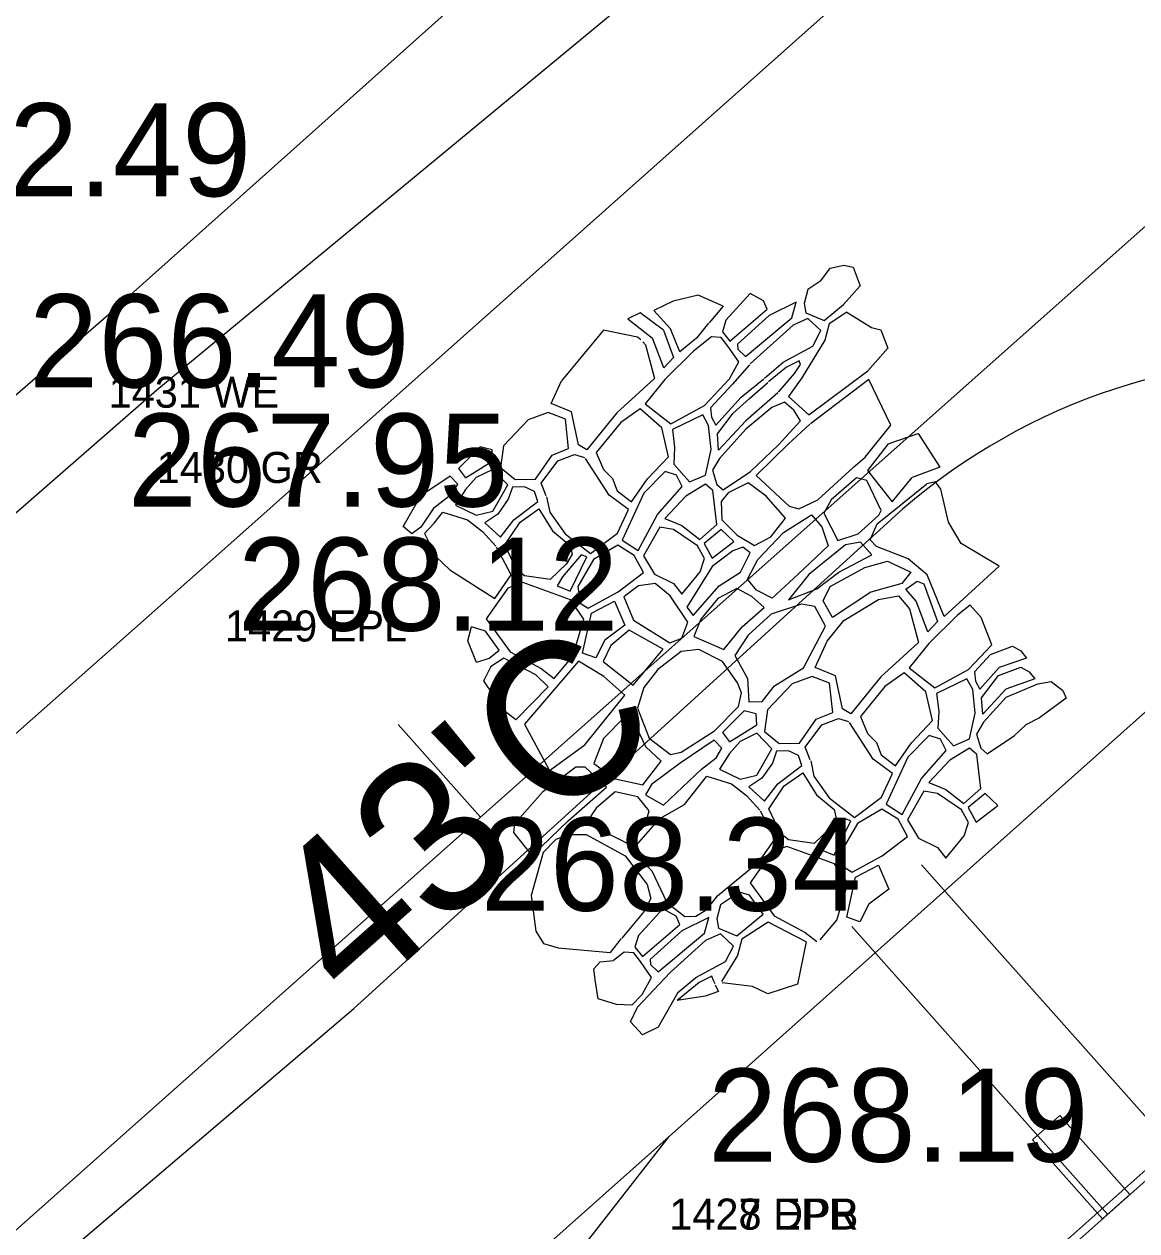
# Model space of a CAD drawing. Extents: x 49683 to 58852, y 49525 to 54803.
# Drawn here: x 55220.91 to 55256.78, y 53061.78 to 53100.69 of the extents above; entities that cross this region are included whole.
import ezdxf

# ---------------------------------------------------------------- set-up
doc = ezdxf.new("R2010")
doc.units = 0
for name, color, linetype in [('Level 1', 7, 'Continuous'), ('Level 10', 7, 'Continuous'), ('Level 15', 7, 'Continuous'), ('Level 18', 7, 'Continuous'), ('Level 27', 7, 'Continuous'), ('Level 3', 7, 'Continuous'), ('Level 32', 7, 'Continuous'), ('Level 48', 7, 'Continuous'), ('Level 53', 7, 'Continuous'), ('Level 57', 7, 'Continuous'), ('Level 58', 7, 'Continuous'), ('Level 60', 7, 'Continuous'), ('Level 7', 7, 'Continuous'), ('Level 8', 7, 'Continuous')]:
    doc.layers.add(name, color=color, linetype=linetype)

msp = doc.modelspace()

# ---------------------------------------------------------------- linework, layer by layer
at = {"layer": 'Level 1'}
for p, q in [((52544.807, 50683.302), (55534.583, 53340.862)), ((55235.619, 53075.118), (55232.962, 53078.107))]:
    msp.add_line(p, q, dxfattribs=at)
at = {"layer": 'Level 10'}
for p, q in [((55223.631, 53091.32), (55261.669, 53125.363)), ((55039.313, 52932.122), (55223.631, 53091.32))]:
    msp.add_line(p, q, dxfattribs=at)
at = {"layer": 'Level 15'}
for p, q in [((55258.079, 53064.31), (55249.837, 53073.583)), ((55255.837, 53062.317), (55247.596, 53071.588)), ((55253.595, 53060.324), (55265.526, 53070.929))]:
    msp.add_line(p, q, dxfattribs=at)
for points in [[(55246.591, 53092.41), (55246.89, 53092.815), (55247.336, 53092.921), (55247.639, 53092.849), (55247.862, 53092.252), (55247.324, 53091.649)], [(55246.591, 53092.41), (55246.175, 53092.126), (55246.052, 53091.685), (55246.113, 53091.379), (55246.701, 53091.134), (55247.324, 53091.649)], [(55242.635, 53091.946), (55241.828, 53091.756), (55241.207, 53091.455), (55241.748, 53090.865)], [(55243.442, 53091.595), (55242.635, 53091.946)], [(55244.313, 53092.002), (55243.528, 53091.143), (55243.417, 53090.763), (55243.662, 53090.469), (55244.864, 53091.5), (55244.741, 53091.769), (55244.313, 53092.002)], [(55243.442, 53091.595), (55242.992, 53091.059)], [(55241.519, 53090.817), (55240.772, 53091.384), (55240.368, 53091.189), (55241.169, 53090.559)], [(55242.976, 53091.044), (55242.587, 53090.557), (55242.049, 53090.124), (55241.748, 53090.865)], [(55244.774, 53089.277), (55245.376, 53089.785), (55246.332, 53090.301), (55246.59, 53090.804), (55246.174, 53091.195), (55245.696, 53090.986), (55244.319, 53089.732)], [(55247.435, 53091.399), (55246.86, 53091.024), (55246.725, 53090.497), (55245.976, 53089.284), (55245.546, 53088.683), (55246.207, 53088.095), (55248.103, 53089.509)], [(55247.435, 53091.399), (55248.226, 53090.906), (55248.53, 53090.834), (55248.752, 53090.237), (55248.103, 53089.509)], [(55240.791, 53090.509), (55240.681, 53090.593), (55239.584, 53090.823), (55238.23, 53089.186)], [(55241.519, 53090.817), (55241.838, 53089.934), (55241.532, 53089.607), (55241.169, 53090.559)], [(55240.853, 53090.449), (55240.943, 53090.344), (55241.226, 53089.259), (55240.013, 53088.151), (55239.052, 53086.959), (55238.779, 53087.127), (55238.559, 53088.191), (55237.895, 53088.454), (55238.23, 53089.186)], [(55244.294, 53089.707), (55243.748, 53089.078), (55243.032, 53088.318), (55243.065, 53088.016), (55243.21, 53087.76), (55244.026, 53088.665), (55244.75, 53089.252)], [(55245.23, 53088.821), (55245.743, 53089.418), (55245.94, 53089.712), (55245.891, 53089.835), (55245.486, 53089.626), (55244.903, 53089.153)], [(55245.205, 53088.796), (55244.171, 53087.895), (55243.298, 53086.955), (55243.265, 53087.48), (55243.769, 53088.14), (55244.295, 53088.621), (55244.885, 53089.136)], [(55247.647, 53086.406), (55248.019, 53086.725), (55248.853, 53087.755), (55248.144, 53089.225), (55246.254, 53087.801)], [(55246.236, 53087.784), (55245.544, 53087.148), (55244.504, 53086.13), (55245.575, 53085.148), (55245.888, 53085.059), (55246.492, 53085.35), (55247.63, 53086.39)], [(55248.765, 53087.151), (55248.094, 53086.296), (55248.891, 53085.29), (55249.54, 53086.071)], [(55248.765, 53087.151), (55249.732, 53087.487), (55250.426, 53086.407), (55249.54, 53086.071)], [(55237.738, 53085.476), (55237.576, 53085.882), (55238.114, 53086.61), (55238.652, 53086.811), (55238.975, 53086.714)], [(55237.753, 53085.449), (55237.853, 53084.954), (55238.354, 53084.256), (55239.162, 53083.62), (55240.033, 53084.27), (55240.389, 53085.043), (55239.765, 53085.495), (55239.002, 53086.685)], [(55234.115, 53085.087), (55234.701, 53085.544), (55234.89, 53085.859), (55234.639, 53086.11), (55233.697, 53085.476)], [(55250.569, 53081.593), (55250.025, 53082.929), (55249.403, 53083.445), (55248.392, 53083.844), (55248.182, 53084.055), (55248.404, 53084.571), (55250.012, 53085.863)], [(55250.569, 53081.593), (55252.339, 53083.212), (55251.119, 53083.942), (55250.704, 53084.634), (55250.463, 53085.695), (55250.287, 53085.935), (55250.012, 53085.863)], [(55234.115, 53085.087), (55233.702, 53084.469), (55233.402, 53084.257), (55233.132, 53084.489), (55233.697, 53085.476)], [(55234.123, 53084.599), (55234.407, 53084.955), (55235.204, 53084.704), (55235.687, 53084.327), (55236.11, 53083.853)], [(55234.123, 53084.599), (55233.815, 53084.263), (55234.188, 53083.514), (55234.636, 53083.097), (55236.079, 53082.169)], [(55236.079, 53082.169), (55236.613, 53082.931), (55236.136, 53083.826)], [(55251.405, 53081.956), (55250.998, 53081.627), (55250.07, 53080.721), (55249.443, 53079.938), (55250.269, 53079.291), (55251.353, 53079.884), (55252.101, 53080.673)], [(55252.101, 53080.673), (55251.766, 53081.551), (55251.405, 53081.956)], [(55235.892, 53080.236), (55235.491, 53080.105), (55235.209, 53080.804), (55235.332, 53081.253)], [(55235.892, 53080.236), (55236.218, 53080.505), (55235.778, 53081.117), (55235.332, 53081.253)], [(55252.064, 53080.359), (55252.774, 53080.628), (55253.04, 53080.481), (55253.221, 53080.249), (55252.344, 53079.939)], [(55237.798, 53079.317), (55237.406, 53079.71), (55236.377, 53080.248), (55235.94, 53079.962)], [(55252.064, 53080.359), (55251.543, 53079.806), (55251.576, 53079.505), (55251.721, 53079.248), (55252.344, 53079.939)], [(55237.798, 53079.317), (55236.756, 53078.255), (55236.376, 53078.557), (55235.726, 53079.518), (55235.96, 53079.984)], [(55252.323, 53079.684), (55253.043, 53079.956), (55253.309, 53079.809), (55253.49, 53079.577), (55252.556, 53079.247)], [(55252.556, 53079.247), (55251.81, 53078.444), (55251.777, 53078.969), (55252.323, 53079.684)], [(55252.569, 53078.99), (55253.583, 53079.412), (55254.016, 53079.496), (55254.399, 53079.206), (55254.5, 53078.957), (55253.646, 53078.323), (55253.2, 53078.097)], [(55252.569, 53078.99), (55251.832, 53078.176), (55251.608, 53077.796), (55251.753, 53077.338), (55251.954, 53077.159), (55252.837, 53077.752), (55253.2, 53078.097)], [(55246.25, 53076.965), (55246.087, 53077.371), (55246.626, 53078.098), (55247.163, 53078.299), (55247.487, 53078.203)], [(55246.265, 53076.938), (55246.364, 53076.443), (55246.866, 53075.745), (55247.674, 53075.109), (55248.544, 53075.759), (55248.9, 53076.531), (55248.276, 53076.984), (55247.514, 53078.174)], [(55238.457, 53075.014), (55239.685, 53076.083), (55238.993, 53076.733), (55238.699, 53076.733), (55237.619, 53075.927)], [(55241.639, 53072.355), (55241.151, 53073.377), (55240.501, 53074.048), (55241.405, 53075.078), (55242.193, 53075.53), (55242.918, 53076.444), (55243.716, 53076.193), (55244.198, 53075.816), (55244.621, 53075.341)], [(55238.457, 53075.014), (55237.289, 53073.881), (55236.7, 53074.625), (55236.724, 53074.918), (55237.619, 53075.927)], [(55241.666, 53072.329), (55242.206, 53071.917), (55242.561, 53071.93), (55242.916, 53072.138), (55243.26, 53072.58), (55244.609, 53073.684), (55245.124, 53074.42), (55244.648, 53075.315)], [(55238.255, 53074.474), (55238.051, 53074.399), (55237.638, 53073.98), (55237.25, 53072.597), (55237.409, 53071.442), (55237.651, 53071.044), (55238.127, 53070.9), (55239.803, 53070.757)], [(55238.255, 53074.474), (55238.434, 53074.56), (55239.022, 53074.56), (55240.28, 53073.869), (55240.993, 53072.946), (55241.108, 53072.495), (55240.877, 53072.054), (55240.174, 53071.219)], [(55246.573, 53071.158), (55247.106, 53071.8), (55247.463, 53072.989), (55247.035, 53073.613), (55245.492, 53074.175), (55245.014, 53073.991), (55244.314, 53072.997), (55245.085, 53071.932), (55246.089, 53071.394), (55246.46, 53071.111)], [(55246.116, 53071.094), (55244.889, 53071.736), (55244.042, 53071.184), (55243.907, 53070.657), (55243.391, 53069.821)], [(55240.159, 53071.204), (55239.803, 53070.757)], [(55241.984, 53069.46), (55242.559, 53069.945), (55243.515, 53070.46), (55243.773, 53070.963), (55243.357, 53071.355), (55242.879, 53071.146), (55241.74, 53070.109)], [(55246.116, 53071.094), (55245.842, 53069.736), (55244.88, 53069.426), (55244.385, 53069.653), (55243.411, 53069.779)], [(55240.495, 53069.052), (55240.009, 53069.075), (55239.411, 53069.26), (55239.312, 53069.877), (55239.272, 53070.226), (55239.482, 53070.458), (55239.913, 53070.496)], [(55240.495, 53069.052), (55240.83, 53069.405), (55241.132, 53069.953), (55240.775, 53070.467), (55240.563, 53070.746), (55240.25, 53070.768), (55239.913, 53070.496)], [(55241.984, 53069.46), (55241.35, 53068.343), (55240.842, 53068.096), (55240.46, 53068.521), (55240.679, 53068.994), (55241.74, 53070.109)], [(55243.185, 53069.744), (55243.122, 53069.872), (55243.073, 53069.994), (55242.669, 53069.786), (55241.959, 53069.21)], [(55243.185, 53069.715), (55243.233, 53069.619), (55243.29, 53069.5), (55242.863, 53069.343), (55241.959, 53069.21)], [(55241.999, 53069.235), (55242.067, 53069.295)]]:
    msp.add_lwpolyline(points, dxfattribs=at)
for points in [[(55244.163, 53089.968), (55245.66, 53091.219), (55245.795, 53091.722), (55244.925, 53091.292), (55243.907, 53090.372), (55243.919, 53090.212)], [(55240.931, 53088.45), (55241.758, 53087.803), (55242.842, 53088.396), (55243.647, 53089.246), (55243.95, 53089.794), (55243.593, 53090.307), (55243.381, 53090.586), (55243.068, 53090.608), (55242.486, 53090.138), (55241.558, 53089.232)], [(55243.442, 53085.671), (55244.325, 53086.264), (55245.231, 53087.125), (55245.936, 53087.897), (55245.724, 53088.243), (55245.423, 53088.499), (55245.009, 53088.331), (55244.171, 53087.627), (55243.32, 53086.687), (55243.096, 53086.307), (55243.241, 53085.849)], [(55237.397, 53086.019), (55237.935, 53086.789), (55238.462, 53087), (55238.358, 53087.949), (55237.8, 53088.169), (55237.157, 53087.926), (55236.365, 53087.093), (55236.27, 53086.387), (55236.733, 53086.008)], [(55240.492, 53085.287), (55241.007, 53086.025), (55241.678, 53086.741), (55241.467, 53087.668), (55240.764, 53088.282), (55240.149, 53087.845), (55239.354, 53086.873), (55239.588, 53086.325), (55239.878, 53086.035), (55240.023, 53085.644)], [(55242.359, 53085.926), (55242.873, 53086.15), (55243.053, 53086.977), (55242.975, 53087.748), (55242.786, 53088.094), (55241.813, 53087.613), (55241.88, 53087.032), (55241.857, 53086.495)], [(55235.132, 53086.058), (55236.015, 53086.605), (55235.994, 53086.962), (55235.606, 53087.056), (55234.912, 53086.363)], [(55234.816, 53085.176), (55235.477, 53084.852), (55236.013, 53084.989), (55236.497, 53085.829), (55236.014, 53086.332), (55235.479, 53086.069), (55235.132, 53085.681)], [(55240.703, 53083.712), (55241.33, 53084.875), (55242.124, 53085.781), (55241.934, 53086.149), (55241.577, 53086.261), (55240.884, 53085.567), (55240.189, 53084.047)], [(55247.138, 53084.043), (55247.792, 53084.254), (55248.457, 53084.856), (55248.541, 53085.004), (55248.078, 53085.973), (55247.741, 53086.056), (55246.929, 53085.349), (55246.686, 53084.917)], [(55236.264, 53084.149), (55236.695, 53084.706), (55237.472, 53085.295), (55237.357, 53085.62), (55237.042, 53085.767), (55236.654, 53085.756), (55236.517, 53085.367), (55236.181, 53084.884), (55235.76, 53084.611)], [(55242.692, 53084.072), (55243.24, 53084.553), (55243.107, 53085.648), (55242.872, 53085.86), (55242.235, 53085.468), (55241.564, 53084.752), (55242.111, 53084.518)], [(55243.375, 53085.291), (55243.396, 53084.71), (55243.898, 53084.207), (55244.457, 53083.873), (55244.982, 53084.153), (55245.452, 53084.757), (55244.827, 53085.471), (55244.247, 53085.895), (55243.61, 53085.57)], [(55236.406, 53083.899), (55236.897, 53084.634), (55237.497, 53085.064), (55237.938, 53084.354), (55238.513, 53083.877), (55238.574, 53083.595), (55238.39, 53083.288), (55237.862, 53082.786), (55237.042, 53082.895), (55236.785, 53083.103)], [(55245.018, 53082.175), (55244.523, 53082.438), (55244.228, 53082.796), (55244.566, 53083.429), (55245.389, 53084.294), (55246.296, 53084.864), (55246.622, 53084.474), (55246.832, 53083.863), (55245.862, 53082.956)], [(55240.877, 53083.549), (55241.232, 53082.949), (55241.844, 53082.655), (55242.113, 53082.313), (55242.702, 53083.024), (55242.837, 53083.453), (55242.617, 53083.869), (55241.846, 53084.395), (55241.405, 53084.468)], [(55243.093, 53083.469), (55243.787, 53084.006), (55243.374, 53084.397), (55242.826, 53083.938)], [(55239.087, 53081.856), (55240.055, 53082.384), (55240.877, 53083.01), (55240.571, 53083.56), (55240.044, 53083.891), (55239.26, 53083.424), (55238.757, 53082.554), (55238.829, 53082.015)], [(55242.477, 53081.625), (55243.316, 53082.576), (55243.998, 53083.012), (55244.311, 53083.638), (55244.077, 53083.828), (55243.753, 53083.705), (55243.093, 53083.201), (55242.276, 53081.893)], [(55245.555, 53082.123), (55246.462, 53082.482), (55247.169, 53083.021), (55248.234, 53083.58), (55247.876, 53083.981), (55247.391, 53083.896), (55246.21, 53082.946)], [(55238.511, 53082.406), (55239.052, 53083.51), (55238.868, 53083.571), (55238.267, 53082.872), (55238.095, 53082.578)], [(55246.967, 53081.556), (55246.662, 53082.093), (55246.894, 53082.557), (55248.012, 53083.169), (55248.739, 53083.37), (55249.498, 53083.013), (55249.202, 53082.654), (55248.201, 53082.368)], [(55235.803, 53081.509), (55236.573, 53080.444), (55237.577, 53079.906), (55237.994, 53079.588), (55238.595, 53080.311), (55238.951, 53081.5), (55238.523, 53082.125), (55236.98, 53082.687), (55236.502, 53082.502)], [(55240.239, 53082.225), (55240.556, 53081.465), (55241.719, 53080.744), (55242.112, 53080.891), (55242.308, 53081.406), (55241.733, 53082.251), (55241.256, 53082.655), (55240.717, 53082.581)], [(55243.467, 53080.519), (55244.058, 53081.257), (55244.765, 53081.88), (55244.365, 53082.238), (55243.88, 53082.49), (55243.268, 53082.173), (55242.72, 53081.498), (55242.498, 53080.939)], [(55250.044, 53081.095), (55249.665, 53082.086), (55249.329, 53082.465), (55249.698, 53082.729), (55249.908, 53082.644), (55250.35, 53081.422)], [(55239.342, 53080.251), (55238.913, 53080.41), (55239.197, 53081.697), (55239.944, 53082.077), (55240.274, 53081.306), (55239.624, 53080.827)], [(55247.564, 53078.447), (55247.29, 53078.616), (55247.07, 53079.68), (55246.406, 53079.942), (55246.797, 53080.797), (55247.336, 53081.461), (55248.453, 53082.137), (55249.096, 53082.254), (55249.454, 53081.832), (55249.738, 53080.747), (55248.524, 53079.639)], [(55244.698, 53078.845), (55245.099, 53079.351), (55246.038, 53079.932), (55246.745, 53081.271), (55246.398, 53081.913), (55245.966, 53081.986), (55244.986, 53081.659), (55244.247, 53080.983), (55243.825, 53080.329), (55244.225, 53079.592), (55244.266, 53078.833)], [(55240.542, 53079.37), (55241.511, 53080.535), (55240.409, 53081.147), (55239.82, 53080.656), (55239.575, 53080.141)], [(55241.743, 53077.135), (55242.09, 53077.209), (55243.161, 53077.903), (55243.939, 53078.681), (55244.034, 53079.132), (55243.908, 53079.447), (55243.426, 53080.14), (55242.66, 53080.527), (55242.093, 53080.463), (55241.337, 53079.875), (55240.885, 53079.297), (55240.685, 53078.635), (55241.062, 53077.67)], [(55237.843, 53076.623), (55238.983, 53077.445), (55240.272, 53079.051), (55239.599, 53079.651), (55238.778, 53080.152), (55237.036, 53078.117)], [(55249.004, 53076.776), (55249.518, 53077.514), (55250.19, 53078.23), (55249.978, 53079.157), (55249.275, 53079.77), (55248.66, 53079.334), (55247.866, 53078.361), (55248.1, 53077.814), (55248.39, 53077.524), (55248.535, 53077.133)], [(55245.908, 53077.507), (55246.447, 53078.277), (55246.974, 53078.489), (55246.87, 53079.437), (55246.311, 53079.658), (55245.668, 53079.415), (55244.877, 53078.581), (55244.781, 53077.875), (55245.244, 53077.496)], [(55250.87, 53077.415), (55251.384, 53077.639), (55251.564, 53078.466), (55251.487, 53079.237), (55251.297, 53079.583), (55250.325, 53079.101), (55250.391, 53078.52), (55250.368, 53077.984)], [(55239.276, 53076.849), (55239.958, 53076.357), (55240.85, 53076.158), (55241.449, 53076.925), (55240.946, 53077.386), (55240.495, 53078.341), (55240.265, 53078.341), (55239.581, 53077.658)], [(55243.644, 53077.547), (55244.526, 53078.094), (55244.505, 53078.451), (55244.117, 53078.545), (55243.424, 53077.851)], [(55243.328, 53076.665), (55243.989, 53076.34), (55244.524, 53076.477), (55245.008, 53077.318), (55244.526, 53077.821), (55243.99, 53077.558), (55243.643, 53077.169)], [(55240.944, 53075.833), (55241.521, 53075.508), (55242.74, 53076.664), (55243.213, 53077.032), (55243.402, 53077.347), (55243.15, 53077.599), (55242.058, 53076.863), (55241.133, 53076.169)], [(55249.214, 53075.201), (55249.841, 53076.363), (55250.635, 53077.269), (55250.446, 53077.638), (55250.089, 53077.749), (55249.395, 53077.056), (55248.701, 53075.535)], [(55244.775, 53075.638), (55245.206, 53076.195), (55245.984, 53076.783), (55245.869, 53077.109), (55245.554, 53077.255), (55245.165, 53077.244), (55245.029, 53076.856), (55244.692, 53076.373), (55244.272, 53076.099)], [(55251.203, 53075.561), (55251.751, 53076.042), (55251.618, 53077.136), (55251.384, 53077.348), (55250.747, 53076.957), (55250.076, 53076.241), (55250.623, 53076.007)], [(55244.917, 53075.387), (55245.408, 53076.123), (55246.009, 53076.552), (55246.449, 53075.842), (55247.025, 53075.365), (55247.085, 53075.084), (55246.901, 53074.777), (55246.374, 53074.274), (55245.553, 53074.383), (55245.296, 53074.591)], [(55239.022, 53074.938), (55240.365, 53074.268), (55240.932, 53074.857), (55241.059, 53075.319), (55240.692, 53075.77), (55239.957, 53075.937), (55239.348, 53075.411)], [(55249.389, 53075.037), (55249.743, 53074.437), (55250.356, 53074.144), (55250.625, 53073.801), (55251.214, 53074.512), (55251.349, 53074.941), (55251.129, 53075.358), (55250.358, 53075.884), (55249.917, 53075.957)], [(55251.605, 53074.958), (55252.298, 53075.495), (55251.885, 53075.885), (55251.337, 53075.427)], [(55247.598, 53073.344), (55248.567, 53073.872), (55249.388, 53074.498), (55249.082, 53075.049), (55248.556, 53075.379), (55247.771, 53074.913), (55247.268, 53074.042), (55247.341, 53073.503)], [(55247.023, 53073.895), (55247.563, 53074.998), (55247.379, 53075.059), (55246.778, 53074.36), (55246.606, 53074.066)], [(55247.854, 53071.74), (55247.425, 53071.898), (55247.708, 53073.185), (55248.456, 53073.566), (55248.786, 53072.794), (55248.136, 53072.316)], [(55244.73, 53071.993), (55244.289, 53072.605), (55243.971, 53072.703), (55243.358, 53072.286), (55243.235, 53071.845), (55243.296, 53071.538), (55243.883, 53071.294)], [(55240.844, 53070.629), (55242.046, 53071.659), (55241.924, 53071.929), (55241.495, 53072.161), (55240.71, 53071.303), (55240.599, 53070.923)], [(55241.346, 53070.127), (55242.842, 53071.379), (55242.977, 53071.881), (55242.107, 53071.451), (55241.089, 53070.531), (55241.101, 53070.372)]]:
    msp.add_lwpolyline(points, close=True, dxfattribs=at)
at = {"layer": 'Level 18'}
for p, q in [((55231.532, 53068.947), (55248.856, 53084.716)), ((55193.446, 53036.534), (55231.532, 53068.947))]:
    msp.add_line(p, q, dxfattribs=at)
msp.add_arc((55262.318, 53069.926), 20, 41.6334, 132.3101, dxfattribs=at)
at = {"layer": 'Level 27'}
for p, q in [((55223.318, 53033.746), (55265.359, 53071.116)), ((55223.484, 53033.559), (55265.526, 53070.929)), ((55253.415, 53064.713), (55254.298, 53065.498)), ((55254.298, 53065.498), (55256.557, 53062.957)), ((55255.673, 53062.172), (55253.415, 53064.713)), ((55256.557, 53062.957), (55255.673, 53062.172))]:
    msp.add_line(p, q, dxfattribs=at)
at = {"layer": 'Level 3'}
for p, q in [((55227.381, 53083.782), (55302.07, 53150.267)), ((55241.707, 53064.82), (55317.341, 53132.327)), ((55048.41, 52925.434), (55227.381, 53083.782)), ((55065.24, 52908.355), (55241.707, 53064.82))]:
    msp.add_line(p, q, dxfattribs=at)
at = {"layer": 'Level 7'}
for p, q in [((55225.184, 53088.894), (55257.638, 53115.728)), ((55042.064, 52929.324), (55225.184, 53088.894))]:
    msp.add_line(p, q, dxfattribs=at)
at = {"layer": 'Level 8'}
msp.add_line((55179.239, 52985.046), (55241.707, 53064.82), dxfattribs=at)

# ---------------------------------------------------------------- texts
at = {"layer": 'Level 32'}
for s, p in [('262.49', (55215.962, 53095.138)), ('266.49', (55221.065, 53088.977)), ('267.95', (55224.249, 53085.132)), ('268.12', (55227.797, 53081.131)), ('268.34', (55235.623, 53072.101)), ('268.19', (55242.954, 53064.008))]:
    msp.add_text(s, height=3, dxfattribs=at).set_placement(p)
at = {"layer": 'Level 48'}
msp.add_text("43'C", height=5, rotation=41.6334, dxfattribs=at).set_placement((55231.532, 53068.947))
at = {"layer": 'Level 53'}
for s, p in [('1429 EPL', (55227.382, 53080.782)), ('1428 EPR', (55241.707, 53061.82))]:
    msp.add_text(s, height=1, dxfattribs=at).set_placement(p)
at = {"layer": 'Level 57'}
msp.add_text('1430 GR', height=1, dxfattribs=at).set_placement((55225.184, 53085.894))
at = {"layer": 'Level 58'}
msp.add_text('1427 DPB', height=1, dxfattribs=at).set_placement((55241.707, 53061.82))
at = {"layer": 'Level 60'}
msp.add_text('1431 WE ', height=1, dxfattribs=at).set_placement((55223.631, 53088.32))

doc.saveas('drawing.dxf')
